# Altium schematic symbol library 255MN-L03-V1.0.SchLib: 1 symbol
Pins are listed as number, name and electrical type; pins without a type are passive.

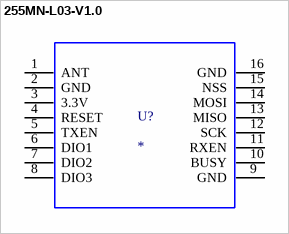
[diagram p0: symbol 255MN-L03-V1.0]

## 255MN-L03-V1.0
designator U?
255MN-L03-V1.0
pins: 1 ANT, 2 GND, 3 3.3V, 4 RESET, 5 TXEN, 6 DIO1, 7 DIO2, 8 DIO3, 9 GND, 10 BUSY, 11 RXEN, 12 SCK, 13 MISO, 14 MOSI, 15 NSS, 16 GND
